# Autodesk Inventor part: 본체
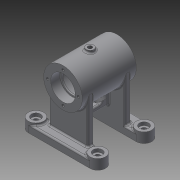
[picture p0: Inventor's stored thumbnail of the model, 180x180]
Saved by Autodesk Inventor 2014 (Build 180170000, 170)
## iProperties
Created: 2015-11
Part Number: 본체
Material: 일반
Document SubType Name: Modeling
Designer: basic
Density: 1 g/cm^3
Appearance: 기본값
Author: basic
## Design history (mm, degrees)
sketch "스케치1"
  geometry: L1 (0, 35)-(0, -35); L2 (0, 35)-(25, 35); L3 (25, -35)-(0, -35); L4 (25, 35)-(25, -35); L5 (16, 35)-(16, 23); L6 (16, 23)-(14, 23); L7 (14, 23)-(14, 21); L8 (14, 21)-(21, 21); L9 (21, 21)-(21, -21); L10 (21, -21)-(14, -21); L11 (14, -21)-(14, -23); L12 (14, -23)-(16, -23); L13 (16, -23)-(16, -35); 2 further points
  constraints: 26 end point, 8 parallel, 4 perpendicular, 2 collinear, 2 point on line, 1 coincident, 1 midpoint, 1 vertical
  dimensions: "d0" = 70 distance of L1.start L1.end; "d1" = 50 diameter of L4 L1; "d2" = 42 diameter of L9 L1; "d3" = 32 diameter of L5 L1; "d4" = 28 diameter of L7 L1; "d5" = 12 distance between parallel lines of L2 L6; "d6" = 2 distance between parallel lines of L8 L6; "d7" = 2 distance between parallel lines of L12 L10; "d8" = 12 distance between parallel lines of L3 L12
revolve "회전1" sketch "스케치1" stored, may be unused: angle "d9" = 90 deg
node "작업 평면2"
sketch "스케치5"
  geometry: L1 (-50, 40)-(50, 40); L2 (50, 40)-(50, 20); L3 (50, 20)-(-50, 20); L4 (-50, 20)-(-50, 40); 1 further point
  constraints: 8 end point, 2 parallel, 1 horizontal, 1 perpendicular
  dimensions: "d32" = 100 distance of L1.end L1.start; "d33" = 20 distance between parallel lines of L3 L1; "d34" = 40 distance from line of point (0, 0) L1; "d35" = 50 distance from line of point (0, 0) L2
extrude "돌출3" join sketch "스케치5" distance "d36" = 10; taper "d37" = 0 deg
fillet "모깎기2" dims "d38" = 10
sketch "스케치6"
  geometry: C1 r 10 at (30, 40); C2 r 10 at (30, -40); A1 r 10 centre (30, 40) between (40, 40) and (20, 40) reference; A2 r 10 centre (30, -40) between (20, -40) and (40, -40) reference; 1 further point
  constraints: 2 centre point, 2 coincident, 1 concentric
  dimensions: "d39" = 20 diameter of C1
extrude "돌출4" join sketch "스케치6" distance "d40" = 3; taper "d41" = 0 deg
sketch "스케치7"
  geometry: L1 (20, 40)-(20, -40) reference; L2 (28, -25)-(20, -25); L3 (20, -25)-(20, 25); L4 (20, 25)-(28, 25); L5 (28, 25)-(28, -25); 1 further point
  constraints: 8 end point, 2 parallel, 1 horizontal, 1 perpendicular, 1 point on line
  dimensions: "d42" = 50 distance between parallel lines of L2 L4; "d43" = 25 distance from line of point (0, 0) L4; "d44" = 8 distance between parallel lines of L1 L5
extrude "돌출5" join sketch "스케치7" stored distance "d45" = 3; taper "d46" = 0 deg
sketch "스케치9"
  geometry: L1 (-21, 21)-(-21, -21) reference; L2 (-21, -21)-(-14, -21) reference; L3 (-14, -21)-(-14, -23) reference; L4 (-14, -23)-(-16, -23) reference; L5 (-16, -23)-(-16, -35) reference; L6 (-16, -35)-(-25, -35) reference; L7 (-25, -35)-(-25, -28) reference; L8 (-25, -28)-(-58, -28) reference; L9 (-58, -28)-(-58, -40) reference; L10 (-58, -40)-(-68, -40) reference; L11 (-68, -40)-(-68, -20) reference; L12 (-68, -20)-(-25, -20) reference; L13 (-25, -20)-(-25, 20) reference; L14 (-25, 20)-(-68, 20) reference; L15 (-68, 20)-(-68, 40) reference; L16 (-68, 40)-(-58, 40) reference; L17 (-58, 40)-(-58, 28) reference; L18 (-58, 28)-(-25, 28) reference; L19 (-25, 28)-(-25, 35) reference; L20 (-25, 35)-(-16, 35) reference; L21 (-16, 35)-(-16, 23) reference; L22 (-16, 23)-(-14, 23) reference; L23 (-14, 23)-(-14, 21) reference; L24 (-14, 21)-(-21, 21) reference; L25 (25, 35)-(25, -35) reference; L26 (25, -35)-(16, -35) reference; L27 (16, -35)-(16, -23) reference; L28 (16, -23)-(14, -23) reference; L29 (14, -23)-(14, -21) reference; L30 (14, -21)-(21, -21) reference; L31 (21, -21)-(21, 21) reference; L32 (21, 21)-(14, 21) reference; L33 (14, 21)-(14, 23) reference; L34 (14, 23)-(16, 23) reference; L35 (16, 23)-(16, 35) reference; L36 (16, 35)-(25, 35) reference; L37 (-23.794, 22)-(-45, 22); L38 (-45, 22)-(-45, -22); L39 (-45, -22)-(-23.794, -22); L40 (-23.794, -22)-(-23.794, 22); 1 further point
  constraints: 8 end point, 2 parallel, 1 horizontal, 1 perpendicular
  dimensions: "d54" = 20 distance between parallel lines of L13 L38; "d55" = 22 distance from line of point (0, 0) L37; "d56" = 44 distance between parallel lines of L39 L37; "d57" = 21.20633 distance between parallel lines of L40 L38
extrude "돌출6" join sketch "스케치9" stored distance "d58" = 8; taper "d59" = 0 deg
sketch "스케치10"
  geometry: L1 (45, -20)-(45, 20) reference; L2 (35, 8)-(35, -8); L3 (31.5, 8)-(31.5, -8); L4 (38.5, -8)-(38.5, 8); L5 (25, -35)-(-25, -35) reference; L6 (68, 20)-(68, 40) reference; A1 r 3.5 centre (35, 8) between (38.5, 8) and (31.5, 8); A2 r 3.5 centre (35, -8) between (31.5, -8) and (38.5, -8); 2 further points
  constraints: 8 end point, 4 point on circle, 4 tangent, 2 centre point, 2 parallel, 1 midpoint
  dimensions: "d60" = 16 distance of L2.start L2.end; "d61" = 7 diameter of A2; "d63" = 35 distance from line of point (35, 0) L5; "d64" = 33 distance from line of L6 point (35, 0)
extrude "돌출7" cut sketch "스케치10" distance "d65" = 8; taper "d66" = 0 deg
sketch "스케치11"
  geometry: C1 r 25 at (0, 0) reference; 1 further point
  constraints: 1 horizontal alignment
  dimensions: "d67" = 20 distance of point (20, 0) C1.centre
hole "구멍1" sketch "스케치11" at (20, 0) diameter "d68" = 3.242; stored, may be unused: countersink angle "d72" = 90 deg, drill point angle "d74" = 118 deg; dims "d69" = 8, "d70" = 4, "d71" = 2, "d73" = 10
node "작업 평면4"
sketch "스케치13"
  geometry: C1 r 5 at (0, 0); 1 further point
  constraints: 1 centre point, 1 coincident
  dimensions: "d79" = 10 diameter of C1
extrude "돌출8" join sketch "스케치13" stored distance "d80" = 8; taper "d81" = 0 deg
sketch "스케치14"
  geometry: C1 r 5 at (0, 0) reference; 1 further point
  constraints: 1 coincident
hole "구멍2" sketch "스케치14" at (0, 0) diameter "d82" = 5.188; stored, may be unused: countersink angle "d86" = 90 deg, drill point angle "d88" = 118 deg; dims "d83" = 8, "d84" = 4, "d85" = 2, "d87" = 10
sketch "스케치18"
  geometry: C1 r 10 at (0, 0) reference; 2 further points
  constraints: 1 coincident
hole "구멍4" sketch "스케치18" at (0, 0) diameter "d102" = 6; stored, may be unused: countersink angle "d106" = 90 deg, drill point angle "d108" = 118 deg; dims "d103" = 8, "d104" = 12, "d105" = 4, "d107" = 10
node "작업 평면9"
fillet "모깎기3" dims "d113" = 0.3
fillet "모깎기4" dims "d114" = 0.3
fillet "모깎기5" dims "d115" = 2
fillet "모깎기6" dims "d116" = 2
fillet "모깎기7" dims "d117" = 2
fillet "모깎기8" dims "d118" = 2
fillet "모깎기9" dims "d119" = 3
fillet "모깎기10" dims "d120" = 2
sketch "스케치21"
  geometry: L1 (25, 35)-(25, -35) reference; L2 (-25, -35)-(25, -35) reference; 2 further points
  constraints: 1 coincident, 1 other
  dimensions: "d121" = 35 distance from line of L2 point (0, 0) (derived); "d122" = 25 distance from line of L1 point (0, 0) (derived)
feature "엠보싱1" sketch "스케치21" dims "d0" = 70, "d1" = 50, "d2" = 42, "d3" = 32, "d4" = 28, "d5" = 12, "d6" = 2, "d7" = 2, "d8" = 12, "d32" = 100, "d33" = 20, "d34" = 40, "d35" = 50, "d123" = 0.5, "d124" = 0
node "작업 평면13"
  node "작업 평면12"
sketch "스케치22"
  geometry: C1 r 6 at (0, 0); 1 further point
  constraints: 1 centre point, 1 coincident
  dimensions: "d128" = 12 diameter of C1
extrude "돌출10" join sketch "스케치22" stored distance "d129" = 8; taper "d130" = 0 deg
sketch "스케치23"
  geometry: C1 r 6 at (0, 0) reference; 1 further point
  constraints: 1 coincident
hole "구멍5" sketch "스케치23" at (0, 0) diameter "d131" = 5.188; stored, may be unused: countersink angle "d135" = 90 deg, drill point angle "d137" = 118 deg; dims "d132" = 8, "d133" = 12, "d134" = 4, "d136" = 10
node "솔리드1"
mirror "대칭2"
pattern_circular "원형 패턴1" dims angle "d76" = 360 deg
mirror "대칭3"
mirror "대칭4"
mirror "대칭5"
mirror "대칭6"
node "절단 모서리 투영2"
other parameters: "d29" = 68, "d78" = -28, "d126" = 30 deg, "d127" = 28
